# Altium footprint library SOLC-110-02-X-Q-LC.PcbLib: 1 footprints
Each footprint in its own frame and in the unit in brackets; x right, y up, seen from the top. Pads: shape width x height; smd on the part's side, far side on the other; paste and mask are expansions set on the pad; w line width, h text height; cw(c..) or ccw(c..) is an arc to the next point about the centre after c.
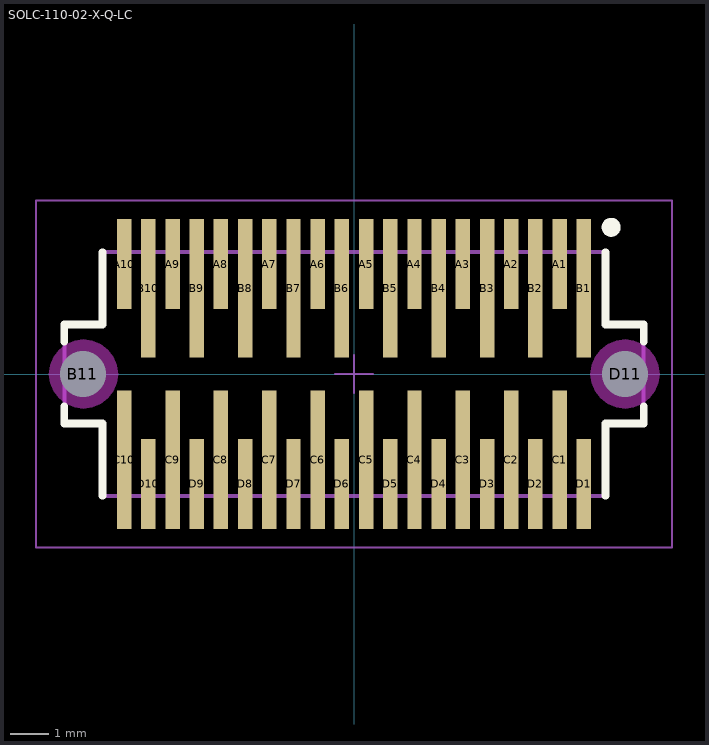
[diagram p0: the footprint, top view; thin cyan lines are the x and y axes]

## SOLC-110-02-X-Q-LC [mm] "1.27mm pitch, 40 pin, socket strip; 4 rows, w/locking clips, SMT"
height 4.62
pads (42):
  rect 0.38x2.36 smd mask+0: A1(5.397,2.885) A2(4.127,2.885) A3(2.857,2.885) A4(1.587,2.885) A5(0.318,2.885) A6(-0.953,2.885) A7(-2.222,2.885) A8(-3.492,2.885) A9(-4.763,2.885) A10(-6.032,2.885) D1(6.032,-2.885) D2(4.763,-2.885) D3(3.492,-2.885) D4(2.222,-2.885) D5(0.953,-2.885) D6(-0.318,-2.885) D7(-1.587,-2.885) D8(-2.857,-2.885) D9(-4.127,-2.885) D10(-5.397,-2.885)
  rect 0.38x3.63 smd mask+0: B1(6.032,2.25) B2(4.763,2.25) B3(3.492,2.25) B4(2.222,2.25) B5(0.953,2.25) B6(-0.318,2.25) B7(-1.587,2.25) B8(-2.857,2.25) B9(-4.127,2.25) B10(-5.397,2.25) C1(5.397,-2.25) C2(4.127,-2.25) C3(2.857,-2.25) C4(1.587,-2.25) C5(0.318,-2.25) C6(-0.953,-2.25) C7(-2.222,-2.25) C8(-3.492,-2.25) C9(-4.763,-2.25) C10(-6.032,-2.25)
  round 1 hole 1.2 unplated mask+0: B11(-7.112,0) D11(7.112,0)
Top Overlay:
  circle w0.25: c6.75,3.85 r0.125
  lines w0.2: -7.6,-0.85 -7.6,-1.3 -6.6,-1.3 -6.6,-3.2 ; -7.6,0.85 -7.6,1.3 -6.6,1.3 -6.6,3.2 ; 6.6,-3.2 6.6,-1.3 7.6,-1.3 7.6,-0.85 ; 6.6,3.2 6.6,1.3 7.6,1.3 7.6,0.85
Keep-Out Layer:
  pour cut-out: -6.191,0 -6.222,0.235 -6.313,0.454 -6.457,0.642 -6.645,0.786 -6.864,0.877 -7.099,0.908 -7.334,0.877 -7.553,0.786 -7.741,0.642 -7.885,0.454 -7.976,0.235 -8.007,0 -7.976,-0.235 -7.885,-0.454 -7.741,-0.642 -7.553,-0.786 -7.334,-0.877 -7.099,-0.908 -6.864,-0.877 -6.645,-0.786 -6.457,-0.642 -6.313,-0.454 -6.222,-0.235
  pour cut-out: 8.02,0 7.989,0.235 7.898,0.454 7.754,0.642 7.566,0.786 7.347,0.877 7.112,0.908 6.877,0.877 6.658,0.786 6.47,0.642 6.326,0.454 6.235,0.235 6.204,0 6.235,-0.235 6.326,-0.454 6.47,-0.642 6.658,-0.786 6.877,-0.877 7.112,-0.908 7.347,-0.877 7.566,-0.786 7.754,-0.642 7.898,-0.454 7.989,-0.235
Mechanical 12:
  lines w0.001: -7.6,-1.3 -6.6,-1.3 -6.6,-3.2 6.6,-3.2 6.6,-1.3 7.6,-1.3 7.6,1.3 6.6,1.3 6.6,3.2 -6.6,3.2 -6.6,1.3 -7.6,1.3 -7.6,-1.3
Mechanical 13:
  lines w0.1: -7.6,-1.3 -6.6,-1.3 -6.6,-3.2 6.6,-3.2 6.6,-1.3 7.6,-1.3 7.6,1.3 6.6,1.3 6.6,3.2 -6.6,3.2 -6.6,1.3 -7.6,1.3 -7.6,-1.3
  text ".Designator" at 0,-0.127 h1.52
Mechanical 15:
  lines w0.05: -0.5,0 0.5,0 ; 0,-0.5 0,0.5 ; -8.35,-4.55 8.35,-4.55 8.35,4.55 -8.35,4.55 -8.35,-4.55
